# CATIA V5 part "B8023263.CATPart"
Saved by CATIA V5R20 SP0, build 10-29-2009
Part number: B8023263
Revision: 6
Definition: design
Nomenclature: B8023263
Source: made
Description: NOT SPECIFIED
Bounding box of the stored display mesh (mm): x -28 to 28, y -28 to 28, z -12 to 63
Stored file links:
  C:\Users\Utente\Desktop\3D files B802\B8023263.CATPart
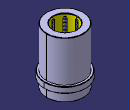
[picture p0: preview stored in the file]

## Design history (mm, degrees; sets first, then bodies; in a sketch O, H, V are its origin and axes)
Body1 "MANIFOLD_SOLID_BREP #38" (main body)
  Solid1: solid without history
Body2 "MANIFOLD_SOLID_BREP #76"
  Solid2: solid without history
Body3 "MANIFOLD_SOLID_BREP #114"
  Solid3: solid without history
Body4 "MANIFOLD_SOLID_BREP #152"
  Solid4: solid without history
Body5 "MANIFOLD_SOLID_BREP #190"
  Solid5: solid without history
Body6 "MANIFOLD_SOLID_BREP #228"
  Solid6: solid without history
Body7 "MANIFOLD_SOLID_BREP #266"
  Solid7: solid without history
Body8 "MANIFOLD_SOLID_BREP #304"
  Solid8: solid without history
Body9 "MANIFOLD_SOLID_BREP #2384"
  Solid9: solid without history
Body10 "MANIFOLD_SOLID_BREP #2422"
  Solid10: solid without history
Body11 "MANIFOLD_SOLID_BREP #2460"
  Solid11: solid without history
Body12 "MANIFOLD_SOLID_BREP #2498"
  Solid12: solid without history
Body13 "MANIFOLD_SOLID_BREP #2536"
  Solid13: solid without history
Body14 "MANIFOLD_SOLID_BREP #2574"
  Solid14: solid without history
Body15 "MANIFOLD_SOLID_BREP #2612"
  Solid15: solid without history
Body16 "MANIFOLD_SOLID_BREP #2650"
  Solid16: solid without history
Body17 "MANIFOLD_SOLID_BREP #2688"
  Solid17: solid without history
Body18 "MANIFOLD_SOLID_BREP #2726"
  Solid18: solid without history
Body19 "MANIFOLD_SOLID_BREP #2764"
  Solid19: solid without history
Body20 "MANIFOLD_SOLID_BREP #2802"
  Solid20: solid without history
Body21 "MANIFOLD_SOLID_BREP #2840"
  Solid21: solid without history
Body22 "MANIFOLD_SOLID_BREP #2878"
  Solid22: solid without history
Body23 "MANIFOLD_SOLID_BREP #2916"
  Solid23: solid without history
Body24 "MANIFOLD_SOLID_BREP #2954"
  Solid24: solid without history
Body25 "MANIFOLD_SOLID_BREP #2992"
  Solid25: solid without history
Body26 "MANIFOLD_SOLID_BREP #3030"
  Solid26: solid without history
Body27 "MANIFOLD_SOLID_BREP #3068"
  Solid27: solid without history
Body28 "MANIFOLD_SOLID_BREP #3106"
  Solid28: solid without history
Body29 "MANIFOLD_SOLID_BREP #3144"
  Solid29: solid without history
Body30 "MANIFOLD_SOLID_BREP #3182"
  Solid30: solid without history
Body31 "MANIFOLD_SOLID_BREP #3220"
  Solid31: solid without history
Body32 "MANIFOLD_SOLID_BREP #3258"
  Solid32: solid without history
Body33 "MANIFOLD_SOLID_BREP #3296"
  Solid33: solid without history
Body34 "MANIFOLD_SOLID_BREP #3334"
  Solid34: solid without history
Body35 "MANIFOLD_SOLID_BREP #3372"
  Solid35: solid without history
Body36 "MANIFOLD_SOLID_BREP #3410"
  Solid36: solid without history
Body37 "MANIFOLD_SOLID_BREP #3448"
  Solid37: solid without history
Body38 "MANIFOLD_SOLID_BREP #3486"
  Solid38: solid without history
Body39 "MANIFOLD_SOLID_BREP #3524"
  Solid39: solid without history
Body40 "MANIFOLD_SOLID_BREP #3562"
  Solid40: solid without history
Body41 "MANIFOLD_SOLID_BREP #3600"
  Solid41: solid without history
Body42 "MANIFOLD_SOLID_BREP #3638"
  Solid42: solid without history
Body43 "MANIFOLD_SOLID_BREP #3676"
  Solid43: solid without history
Body44 "MANIFOLD_SOLID_BREP #3714"
  Solid44: solid without history
Body45 "MANIFOLD_SOLID_BREP #3752"
  Solid45: solid without history
Body46 "MANIFOLD_SOLID_BREP #3790"
  Solid46: solid without history
Body47 "MANIFOLD_SOLID_BREP #3828"
  Solid47: solid without history
Body48 "MANIFOLD_SOLID_BREP #3866"
  Solid48: solid without history
Body49 "MANIFOLD_SOLID_BREP #3904"
  Solid49: solid without history
Body50 "MANIFOLD_SOLID_BREP #3942"
  Solid50: solid without history
Body51 "MANIFOLD_SOLID_BREP #3980"
  Solid51: solid without history
Body52 "MANIFOLD_SOLID_BREP #4018"
  Solid52: solid without history
Body53 "MANIFOLD_SOLID_BREP #4056"
  Solid53: solid without history
Body54 "MANIFOLD_SOLID_BREP #4094"
  Solid54: solid without history
Body55 "MANIFOLD_SOLID_BREP #4132"
  Solid55: solid without history
Body56 "MANIFOLD_SOLID_BREP #4170"
  Solid56: solid without history
Body57 "MANIFOLD_SOLID_BREP #4208"
  Solid57: solid without history
Body58 "MANIFOLD_SOLID_BREP #4246"
  Solid58: solid without history
Body59 "MANIFOLD_SOLID_BREP #4284"
  Solid59: solid without history
Body60 "MANIFOLD_SOLID_BREP #4322"
  Solid60: solid without history
Body61 "MANIFOLD_SOLID_BREP #4360"
  Solid61: solid without history
Body62 "MANIFOLD_SOLID_BREP #4398"
  Solid62: solid without history
Body63 "MANIFOLD_SOLID_BREP #4436"
  Solid63: solid without history
Body64 "MANIFOLD_SOLID_BREP #4474"
  Solid64: solid without history
Body65 "MANIFOLD_SOLID_BREP #4512"
  Solid65: solid without history
Body66 "MANIFOLD_SOLID_BREP #4550"
  Solid66: solid without history
Body67 "MANIFOLD_SOLID_BREP #4588"
  Solid67: solid without history
Body68 "MANIFOLD_SOLID_BREP #4626"
  Solid68: solid without history
Body69 "MANIFOLD_SOLID_BREP #4664"
  Solid69: solid without history
Body70 "MANIFOLD_SOLID_BREP #4702"
  Solid70: solid without history
Body71 "MANIFOLD_SOLID_BREP #4740"
  Solid71: solid without history
Body72 "MANIFOLD_SOLID_BREP #4778"
  Solid72: solid without history
Body73 "MANIFOLD_SOLID_BREP #4816"
  Solid73: solid without history
Body74 "MANIFOLD_SOLID_BREP #4854"
  Solid74: solid without history
Body75 "MANIFOLD_SOLID_BREP #4892"
  Solid75: solid without history
Body76 "MANIFOLD_SOLID_BREP #4930"
  Solid76: solid without history
Body77 "MANIFOLD_SOLID_BREP #4968"
  Solid77: solid without history
Body78 "MANIFOLD_SOLID_BREP #5006"
  Solid78: solid without history
Body79 "MANIFOLD_SOLID_BREP #5044"
  Solid79: solid without history
Body80 "MANIFOLD_SOLID_BREP #5082"
  Solid80: solid without history
Body81 "MANIFOLD_SOLID_BREP #5120"
  Solid81: solid without history
Body82 "MANIFOLD_SOLID_BREP #5158"
  Solid82: solid without history
Body83 "MANIFOLD_SOLID_BREP #5196"
  Solid83: solid without history
Body84 "MANIFOLD_SOLID_BREP #5234"
  Solid84: solid without history
Body85 "MANIFOLD_SOLID_BREP #5272"
  Solid85: solid without history
Body86 "MANIFOLD_SOLID_BREP #5310"
  Solid86: solid without history
Body87 "MANIFOLD_SOLID_BREP #5348"
  Solid87: solid without history
Body88 "MANIFOLD_SOLID_BREP #5386"
  Solid88: solid without history
Body89 "MANIFOLD_SOLID_BREP #5424"
  Solid89: solid without history
Body90 "MANIFOLD_SOLID_BREP #5462"
  Solid90: solid without history
Body91 "MANIFOLD_SOLID_BREP #5500"
  Solid91: solid without history
Body92 "MANIFOLD_SOLID_BREP #5538"
  Solid92: solid without history
Body93 "MANIFOLD_SOLID_BREP #5576"
  Solid93: solid without history
Body94 "MANIFOLD_SOLID_BREP #5614"
  Solid94: solid without history
Body95 "MANIFOLD_SOLID_BREP #5652"
  Solid95: solid without history
Body96 "MANIFOLD_SOLID_BREP #5690"
  Solid96: solid without history
Body97 "MANIFOLD_SOLID_BREP #5728"
  Solid97: solid without history
Body98 "MANIFOLD_SOLID_BREP #5766"
  Solid98: solid without history
Body99 "MANIFOLD_SOLID_BREP #5804"
  Solid99: solid without history
Body100 "MANIFOLD_SOLID_BREP #5842"
  Solid100: solid without history
Body101 "MANIFOLD_SOLID_BREP #5880"
  Solid101: solid without history
Body102 "MANIFOLD_SOLID_BREP #5918"
  Solid102: solid without history
Body103 "MANIFOLD_SOLID_BREP #5956"
  Solid103: solid without history
Body104 "MANIFOLD_SOLID_BREP #5994"
  Solid104: solid without history
Body105 "MANIFOLD_SOLID_BREP #6032"
  Solid105: solid without history
Body106 "MANIFOLD_SOLID_BREP #6070"
  Solid106: solid without history
Body107 "MANIFOLD_SOLID_BREP #6108"
  Solid107: solid without history
Body108 "MANIFOLD_SOLID_BREP #6146"
  Solid108: solid without history
Body109 "MANIFOLD_SOLID_BREP #6184"
  Solid109: solid without history
Body110 "MANIFOLD_SOLID_BREP #6222"
  Solid110: solid without history
Body111 "MANIFOLD_SOLID_BREP #6260"
  Solid111: solid without history
Body112 "MANIFOLD_SOLID_BREP #6298"
  Solid112: solid without history
Body113 "MANIFOLD_SOLID_BREP #6336"
  Solid113: solid without history
Body114 "MANIFOLD_SOLID_BREP #6374"
  Solid114: solid without history
Body115 "MANIFOLD_SOLID_BREP #6412"
  Solid115: solid without history
Body116 "MANIFOLD_SOLID_BREP #6450"
  Solid116: solid without history
Body117 "MANIFOLD_SOLID_BREP #6488"
  Solid117: solid without history
Body118 "MANIFOLD_SOLID_BREP #6526"
  Solid118: solid without history
Body119 "MANIFOLD_SOLID_BREP #6564"
  Solid119: solid without history
Body120 "MANIFOLD_SOLID_BREP #6602"
  Solid120: solid without history
Body121 "MANIFOLD_SOLID_BREP #6640"
  Solid121: solid without history
Body122 "MANIFOLD_SOLID_BREP #6678"
  Solid122: solid without history
Body123 "MANIFOLD_SOLID_BREP #6716"
  Solid123: solid without history
Body124 "MANIFOLD_SOLID_BREP #6754"
  Solid124: solid without history
Body125 "MANIFOLD_SOLID_BREP #6792"
  Solid125: solid without history
Body126 "MANIFOLD_SOLID_BREP #6830"
  Solid126: solid without history
Body127 "MANIFOLD_SOLID_BREP #6868"
  Solid127: solid without history
Body128 "MANIFOLD_SOLID_BREP #6906"
  Solid128: solid without history
Body129 "MANIFOLD_SOLID_BREP #6944"
  Solid129: solid without history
